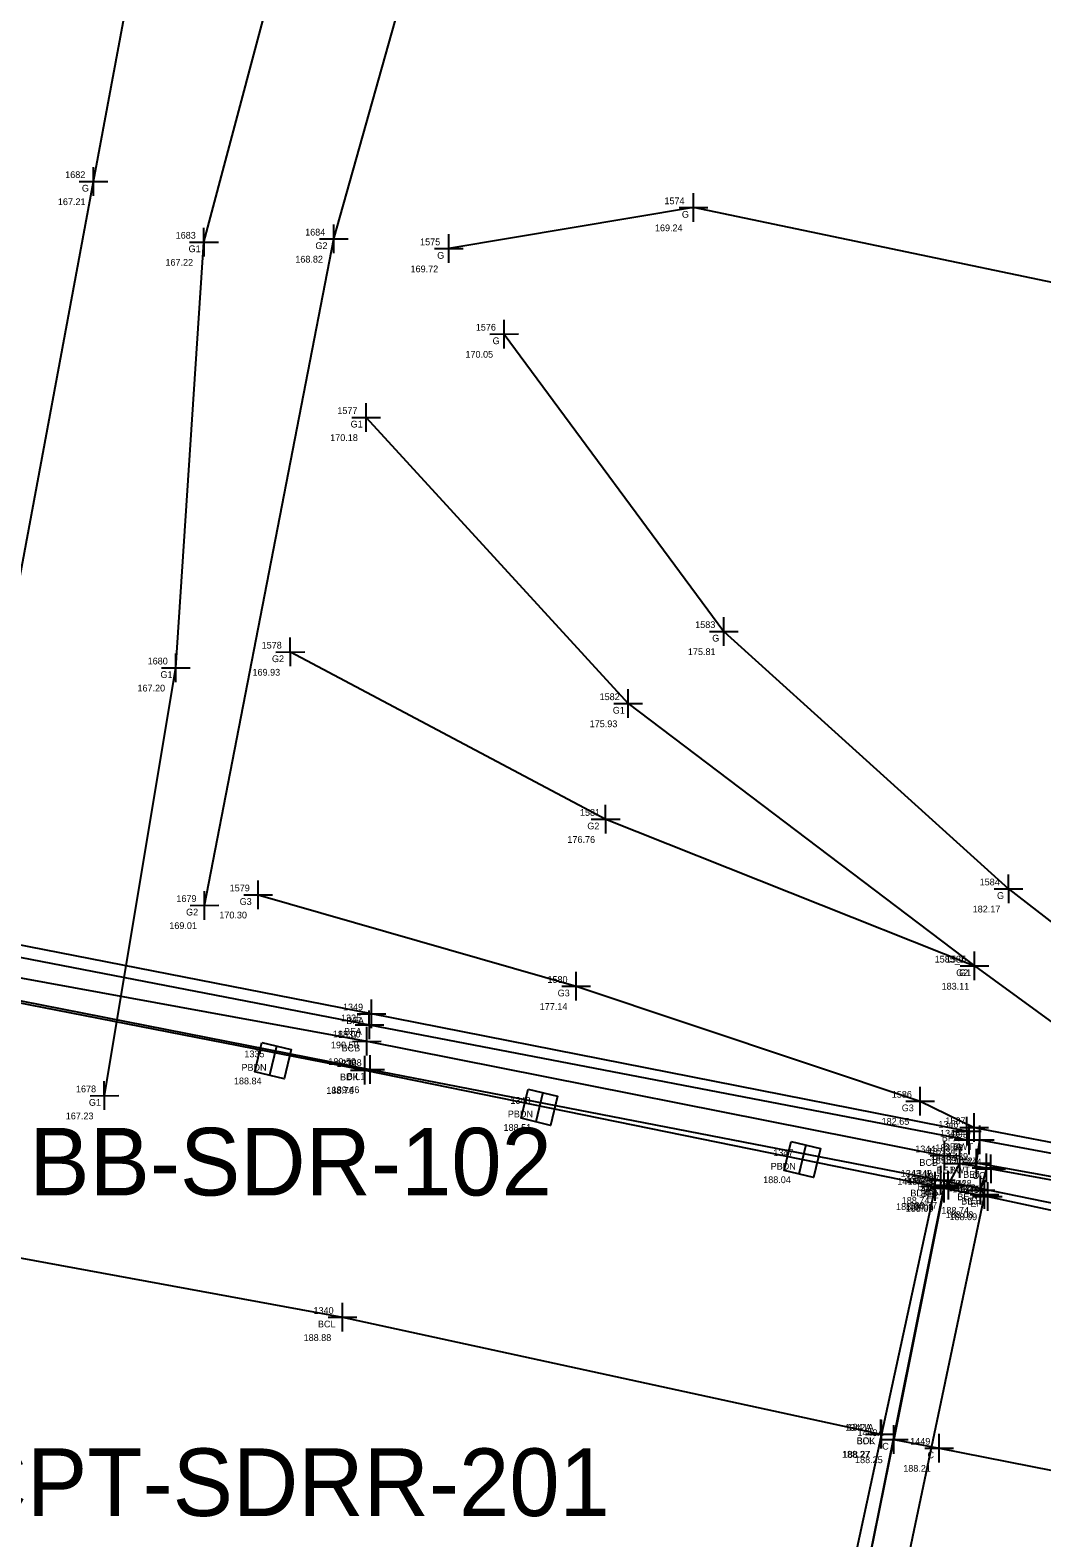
# Model space of a CAD drawing. Extents: x 1157913 to 1159198, y 600595 to 601244.
# Drawn here: x 1158682.7 to 1158727.6, y 600886 to 600952.9 of the extents above; entities that cross this region are included whole.
import ezdxf

# ---------------------------------------------------------------- set-up
doc = ezdxf.new("R2010")
doc.units = 0
for name, color, linetype in [('Default', 7, 'Continuous'), ('S_Bridge_Centerline', 7, 'Continuous'), ('S_Bridge_Curb', 7, 'Continuous'), ('S_Bridge_Deck', 7, 'Continuous'), ('S_Bridge_Downspout', 7, 'Continuous'), ('S_Bridge_ExpansionJoint', 7, 'Continuous'), ('S_Bridge_Fascia', 7, 'Continuous'), ('S_Bridge_Rail', 7, 'Continuous'), ('S_Bridge_Wingwall', 7, 'Continuous'), ('S_Curb_Type_2', 7, 'Continuous'), ('S_Field_Code', 7, 'Continuous'), ('S_Ground_Elevation', 7, 'Continuous'), ('S_Ground_LevelString', 7, 'Continuous'), ('S_Guardrail_Beam', 7, 'Continuous'), ('S_Point_Elevation', 7, 'Continuous'), ('S_Point_Name', 7, 'Continuous'), ('S_Roadway_Centerline', 7, 'Continuous'), ('S_Roadway_Edge_Pavement', 7, 'Continuous'), ('S_Survey_Shot', 7, 'Continuous'), ('S_Text', 7, 'Continuous')]:
    doc.layers.add(name, color=color, linetype=linetype)

msp = doc.modelspace()

# ---------------------------------------------------------------- linework, layer by layer
at = {"layer": 'Default'}
for p, q in [((1158693.515, 600907.201), (1158693.515, 600907.201)), ((1158705.332, 600905.136), (1158705.332, 600905.136)), ((1158716.992, 600902.818), (1158716.992, 600902.818))]:
    msp.add_line(p, q, dxfattribs=at)
at = {"layer": 'S_Bridge_Centerline'}
msp.add_lwpolyline([(1158481.195, 600937.121), (1158507.351, 600932.296), (1158531.006, 600927.652), (1158554.323, 600923.112), (1158577.507, 600918.68), (1158601.407, 600914.027), (1158625.013, 600909.477), (1158647.737, 600904.925), (1158672.228, 600900.301), (1158696.593, 600895.817), (1158720.484, 600890.638)], dxfattribs=at)
at = {"layer": 'S_Bridge_Curb'}
msp.add_lwpolyline([(1158483.161, 600950.18), (1158509.184, 600944.847), (1158532.763, 600940.379), (1158556.45, 600935.563), (1158579.829, 600931.057), (1158603.376, 600926.445), (1158626.911, 600921.776), (1158650.768, 600917.187), (1158674.064, 600912.392), (1158697.671, 600908.06), (1158723.302, 600902.985)], dxfattribs=at)
at = {"layer": 'S_Bridge_Deck'}
msp.add_lwpolyline([(1158483.154, 600948.642), (1158508.91, 600943.661), (1158532.625, 600939.025), (1158556.015, 600934.45), (1158579.602, 600929.788), (1158603.216, 600925.172), (1158626.871, 600920.52), (1158650.274, 600915.846), (1158673.938, 600911.396), (1158697.587, 600906.777), (1158722.887, 600901.626), (1158720.511, 600890.631), (1158717.86, 600878.361), (1158692.562, 600883.367), (1158669.405, 600887.913), (1158645.122, 600892.525), (1158622.108, 600897.299), (1158598.216, 600901.842), (1158574.819, 600906.519), (1158551.011, 600911.144), (1158527.523, 600915.567), (1158503.608, 600920.228), (1158478.738, 600925.244), (1158480.987, 600937.158)], close=True, dxfattribs=at)
at = {"layer": 'S_Bridge_Downspout'}
for p, q in [((1158693.67, 600907.849), (1158693.359, 600906.553)), ((1158705.487, 600905.784), (1158705.176, 600904.488)), ((1158717.147, 600903.466), (1158716.836, 600902.169))]:
    msp.add_line(p, q, dxfattribs=at)
for points in [[(1158693.022, 600908.005), (1158694.319, 600907.694), (1158694.007, 600906.397), (1158692.711, 600906.708)], [(1158704.839, 600905.94), (1158706.136, 600905.629), (1158705.824, 600904.332), (1158704.528, 600904.644)], [(1158716.499, 600903.622), (1158717.796, 600903.31), (1158717.484, 600902.014), (1158716.188, 600902.325)]]:
    msp.add_lwpolyline(points, close=True, dxfattribs=at)
at = {"layer": 'S_Bridge_ExpansionJoint'}
msp.add_lwpolyline([(1158725.16, 600902.453), (1158724.901, 600901.46), (1158725.074, 600901.268), (1158720.121, 600877.707), (1158720.119, 600877.751), (1158719.866, 600876.577), (1158718.73, 600876.808), (1158718.834, 600877.869), (1158718.598, 600878.263), (1158723.284, 600901.606), (1158723.471, 600901.679), (1158723.981, 600902.642)], close=True, dxfattribs=at)
at = {"layer": 'S_Bridge_Fascia'}
msp.add_lwpolyline([(1158482.861, 600951.354), (1158482.898, 600951.287), (1158509.367, 600945.979), (1158532.925, 600941.176), (1158556.366, 600936.562), (1158579.862, 600931.952), (1158603.5, 600927.221), (1158627.041, 600922.676), (1158650.576, 600918.007), (1158674.159, 600913.359), (1158697.787, 600908.797), (1158724.39, 600903.681), (1158724.298, 600904.075), (1158697.887, 600909.28), (1158674.374, 600913.874), (1158650.514, 600918.558), (1158627.158, 600923.073), (1158603.563, 600927.819), (1158579.96, 600932.392), (1158556.434, 600937.017), (1158532.882, 600941.581), (1158509.466, 600946.154)], close=True, dxfattribs=at)
at = {"layer": 'S_Bridge_Rail'}
msp.add_lwpolyline([(1158482.805, 600948.902), (1158509.002, 600943.778), (1158532.726, 600939.143), (1158579.85, 600929.84), (1158603.334, 600925.337), (1158626.819, 600920.746), (1158650.464, 600916.056), (1158674.206, 600911.454), (1158697.827, 600906.811), (1158723.142, 600901.902)], dxfattribs=at)
at = {"layer": 'S_Bridge_Wingwall'}
msp.add_lwpolyline([(1158724.724, 600902.653), (1158724.864, 600903.69), (1158734.549, 600901.881), (1158734.38, 600900.915)], close=True, dxfattribs=at)
at = {"layer": 'S_Curb_Type_2'}
msp.add_lwpolyline([(1158725.365, 600902.406), (1158734.123, 600900.806)], dxfattribs=at)
at = {"layer": 'S_Ground_Elevation'}
for points in [[(1158677.11, 600904.725), (1158681.901, 600926.567), (1158685.55, 600946.209), (1158690.749, 600974.108), (1158693.147, 600986.071), (1158701.123, 601024.221), (1158705.062, 601044.921), (1158714.653, 601091.459), (1158722.945, 601141.975), (1158734.939, 601204.822)], [(1158686.031, 600905.649), (1158689.206, 600924.63), (1158690.452, 600943.52), (1158697.926, 600971.62), (1158698.862, 600985.91), (1158705.062, 601022.477), (1158708.833, 601044.151), (1158718.556, 601089.986), (1158726.939, 601141.559), (1158739.749, 601204.844)], [(1158690.473, 600914.092), (1158696.21, 600943.659), (1158700.07, 600957.392), (1158701.342, 600965.961), (1158702.799, 600967.609), (1158714.854, 600964.534), (1158729.595, 600958.711)], [(1159148.387, 600827.64), (1159092.305, 600843.388), (1159023.639, 600857.423), (1158956.467, 600873.915), (1158901.674, 600888.215), (1158826.796, 600914.424), (1158787.654, 600925.882), (1158774.944, 600931.981), (1158737.918, 600939.668), (1158712.165, 600945.049), (1158701.311, 600943.228)], [(1158703.769, 600939.439), (1158713.512, 600926.246), (1158726.146, 600914.827), (1158737.183, 600906.281)], [(1158697.641, 600935.742), (1158709.272, 600923.047), (1158724.634, 600911.404), (1158732.975, 600905.326)], [(1158694.282, 600925.333), (1158708.271, 600917.914), (1158724.634, 600911.404)], [(1158692.85, 600914.562), (1158706.956, 600910.503), (1158722.22, 600905.407), (1158724.615, 600904.235), (1158733.258, 600902.581), (1158734.697, 600902.369), (1158734.457, 600900.754)]]:
    msp.add_lwpolyline(points, dxfattribs=at)
at = {"layer": 'S_Ground_LevelString'}
msp.add_line((1158723.29, 600901.545), (1158723.29, 600901.545), dxfattribs=at)
for points in [[(1158723.29, 600901.545), (1158721.055, 600890.395)], [(1158718.555, 600878.077), (1158721.055, 600890.395)]]:
    msp.add_lwpolyline(points, dxfattribs=at)
at = {"layer": 'S_Guardrail_Beam'}
msp.add_lwpolyline([(1158723.142, 600901.902), (1158735.673, 600899.33), (1158779.708, 600892.778), (1158821.057, 600885.008), (1158872.579, 600874.816), (1158921.179, 600864.906), (1158974.289, 600854.576), (1159026.528, 600844.124), (1159039.988, 600841.695), (1159053.262, 600839.632), (1159065.358, 600838.096), (1159078.578, 600837.332)], dxfattribs=at)
at = {"layer": 'S_Roadway_Centerline'}
msp.add_lwpolyline([(1158721.055, 600890.395), (1158723.064, 600890.013), (1158776.46, 600879.509), (1158819.528, 600871.149), (1158868.15, 600861.085), (1158918.713, 600851.111), (1158970.46, 600840.7), (1159022.781, 600830.456), (1159075.358, 600819.935), (1159137.497, 600807.122), (1159188.145, 600796.962)], dxfattribs=at)
at = {"layer": 'S_Roadway_Edge_Pavement'}
msp.add_lwpolyline([(1158723.29, 600901.545), (1158725.228, 600901.176), (1158730.919, 600899.955), (1158734.277, 600898.718), (1158779.347, 600889.226), (1158821.037, 600881.144), (1158871.084, 600871.138), (1158921.105, 600861.196), (1158972.945, 600850.848), (1159025.625, 600840.648), (1159077.094, 600830.514), (1159119.992, 600821.415), (1159145.866, 600816.084), (1159193.179, 600806.656)], dxfattribs=at)
at = {"layer": 'S_Survey_Shot'}
for p, q in [((1158685.552, 600945.573), (1158685.549, 600946.846)), ((1158684.914, 600946.208), (1158686.187, 600946.211)), ((1158685.55, 600946.209), (1158685.55, 600946.209)), ((1158712.166, 600944.413), (1158712.164, 600945.685)), ((1158711.529, 600945.048), (1158712.801, 600945.05)), ((1158712.165, 600945.049), (1158712.165, 600945.049)), ((1158690.453, 600942.883), (1158690.45, 600944.156)), ((1158696.211, 600943.023), (1158696.208, 600944.296)), ((1158689.816, 600943.518), (1158691.088, 600943.521)), ((1158690.452, 600943.52), (1158690.452, 600943.52)), ((1158695.574, 600943.658), (1158696.846, 600943.661)), ((1158696.21, 600943.659), (1158696.21, 600943.659)), ((1158701.312, 600942.592), (1158701.309, 600943.865)), ((1158700.674, 600943.227), (1158701.947, 600943.23)), ((1158701.311, 600943.228), (1158701.311, 600943.228)), ((1158703.77, 600938.803), (1158703.768, 600940.076)), ((1158703.133, 600939.438), (1158704.405, 600939.441)), ((1158703.769, 600939.439), (1158703.769, 600939.439)), ((1158697.643, 600935.105), (1158697.64, 600936.378)), ((1158697.005, 600935.74), (1158698.278, 600935.743)), ((1158697.641, 600935.742), (1158697.641, 600935.742)), ((1158713.514, 600925.61), (1158713.511, 600926.883)), ((1158712.876, 600926.245), (1158714.149, 600926.248)), ((1158713.512, 600926.246), (1158713.512, 600926.246)), ((1158694.283, 600924.697), (1158694.281, 600925.969)), ((1158689.207, 600923.993), (1158689.205, 600925.266)), ((1158693.646, 600925.332), (1158694.918, 600925.334)), ((1158694.282, 600925.333), (1158694.282, 600925.333)), ((1158688.57, 600924.628), (1158689.842, 600924.631)), ((1158689.206, 600924.63), (1158689.206, 600924.63)), ((1158709.274, 600922.411), (1158709.271, 600923.683)), ((1158708.636, 600923.046), (1158709.908, 600923.049)), ((1158709.272, 600923.047), (1158709.272, 600923.047)), ((1158708.272, 600917.278), (1158708.269, 600918.55)), ((1158707.634, 600917.913), (1158708.907, 600917.915)), ((1158708.271, 600917.914), (1158708.271, 600917.914)), ((1158726.148, 600914.191), (1158726.145, 600915.464)), ((1158690.474, 600913.456), (1158690.472, 600914.728)), ((1158692.852, 600913.925), (1158692.849, 600915.198)), ((1158725.51, 600914.826), (1158726.783, 600914.829)), ((1158726.146, 600914.827), (1158726.146, 600914.827)), ((1158689.837, 600914.091), (1158691.109, 600914.094)), ((1158690.473, 600914.092), (1158690.473, 600914.092)), ((1158692.214, 600914.56), (1158693.487, 600914.563)), ((1158692.85, 600914.562), (1158692.85, 600914.562)), ((1158724.636, 600910.767), (1158724.633, 600912.04)), ((1158724.636, 600910.767), (1158724.633, 600912.04)), ((1158723.998, 600911.402), (1158725.27, 600911.405)), ((1158723.998, 600911.402), (1158725.27, 600911.405)), ((1158724.634, 600911.404), (1158724.634, 600911.404)), ((1158724.634, 600911.404), (1158724.634, 600911.404)), ((1158706.958, 600909.867), (1158706.955, 600911.139)), ((1158706.32, 600910.502), (1158707.593, 600910.504)), ((1158706.956, 600910.503), (1158706.956, 600910.503)), ((1158697.788, 600908.161), (1158697.785, 600909.433)), ((1158697.889, 600908.644), (1158697.886, 600909.916)), ((1158697.151, 600908.796), (1158698.423, 600908.798)), ((1158697.251, 600909.279), (1158698.524, 600909.282)), ((1158697.672, 600907.424), (1158697.67, 600908.696)), ((1158697.787, 600908.797), (1158697.787, 600908.797)), ((1158697.887, 600909.28), (1158697.887, 600909.28)), ((1158697.035, 600908.059), (1158698.307, 600908.062)), ((1158697.671, 600908.06), (1158697.671, 600908.06)), ((1158697.588, 600906.141), (1158697.586, 600907.414)), ((1158697.828, 600906.175), (1158697.825, 600907.447)), ((1158696.951, 600906.776), (1158698.223, 600906.779)), ((1158697.191, 600906.81), (1158698.463, 600906.813)), ((1158697.587, 600906.777), (1158697.587, 600906.777)), ((1158697.827, 600906.811), (1158697.827, 600906.811)), ((1158686.032, 600905.013), (1158686.03, 600906.285)), ((1158722.221, 600904.771), (1158722.219, 600906.043)), ((1158685.395, 600905.648), (1158686.667, 600905.65)), ((1158686.031, 600905.649), (1158686.031, 600905.649)), ((1158721.584, 600905.406), (1158722.856, 600905.408)), ((1158722.22, 600905.407), (1158722.22, 600905.407)), ((1158724.3, 600903.439), (1158724.297, 600904.711)), ((1158724.616, 600903.599), (1158724.613, 600904.871)), ((1158723.662, 600904.074), (1158724.935, 600904.076)), ((1158723.979, 600904.234), (1158725.251, 600904.236)), ((1158724.298, 600904.075), (1158724.298, 600904.075)), ((1158724.391, 600903.045), (1158724.389, 600904.317)), ((1158724.615, 600904.235), (1158724.615, 600904.235)), ((1158724.866, 600903.054), (1158724.863, 600904.326)), ((1158723.304, 600902.349), (1158723.301, 600903.622)), ((1158723.754, 600903.679), (1158725.026, 600903.682)), ((1158724.228, 600903.689), (1158725.501, 600903.691)), ((1158724.39, 600903.681), (1158724.39, 600903.681)), ((1158724.725, 600902.017), (1158724.722, 600903.29)), ((1158724.864, 600903.69), (1158724.864, 600903.69)), ((1158722.666, 600902.984), (1158723.939, 600902.987)), ((1158723.302, 600902.985), (1158723.302, 600902.985)), ((1158723.345, 600902.64), (1158724.617, 600902.643)), ((1158723.983, 600902.005), (1158723.98, 600903.278)), ((1158723.981, 600902.642), (1158723.981, 600902.642)), ((1158724.087, 600902.652), (1158725.36, 600902.655)), ((1158724.724, 600902.653), (1158724.724, 600902.653)), ((1158725.161, 600901.817), (1158725.159, 600903.089)), ((1158725.367, 600901.77), (1158725.364, 600903.042)), ((1158722.889, 600900.989), (1158722.886, 600902.262)), ((1158723.144, 600901.266), (1158723.141, 600902.539)), ((1158723.144, 600901.266), (1158723.141, 600902.539)), ((1158723.286, 600900.969), (1158723.283, 600902.242)), ((1158723.291, 600900.908), (1158723.289, 600902.181)), ((1158723.291, 600900.908), (1158723.289, 600902.181)), ((1158723.473, 600901.043), (1158723.47, 600902.316)), ((1158724.524, 600902.452), (1158725.796, 600902.454)), ((1158724.729, 600902.405), (1158726.001, 600902.408)), ((1158724.903, 600900.824), (1158724.9, 600902.097)), ((1158725.16, 600902.453), (1158725.16, 600902.453)), ((1158725.365, 600902.406), (1158725.365, 600902.406)), ((1158722.251, 600901.624), (1158723.524, 600901.627)), ((1158722.506, 600901.901), (1158723.779, 600901.904)), ((1158722.506, 600901.901), (1158723.779, 600901.904)), ((1158722.648, 600901.604), (1158723.92, 600901.607)), ((1158722.654, 600901.543), (1158723.926, 600901.546)), ((1158722.654, 600901.543), (1158723.926, 600901.546)), ((1158722.835, 600901.678), (1158724.108, 600901.681)), ((1158722.887, 600901.626), (1158722.887, 600901.626)), ((1158723.142, 600901.902), (1158723.142, 600901.902)), ((1158723.142, 600901.902), (1158723.142, 600901.902)), ((1158723.284, 600901.606), (1158723.284, 600901.606)), ((1158723.29, 600901.545), (1158723.29, 600901.545)), ((1158723.29, 600901.545), (1158723.29, 600901.545)), ((1158723.471, 600901.679), (1158723.471, 600901.679)), ((1158724.265, 600901.459), (1158725.537, 600901.462)), ((1158724.901, 600901.46), (1158724.901, 600901.46)), ((1158725.075, 600900.632), (1158725.073, 600901.905)), ((1158725.23, 600900.54), (1158725.227, 600901.812)), ((1158724.438, 600901.267), (1158725.71, 600901.27)), ((1158724.592, 600901.174), (1158725.865, 600901.177)), ((1158725.074, 600901.268), (1158725.074, 600901.268)), ((1158725.228, 600901.176), (1158725.228, 600901.176)), ((1158696.594, 600895.181), (1158696.591, 600896.453)), ((1158695.957, 600895.816), (1158697.229, 600895.819)), ((1158696.593, 600895.817), (1158696.593, 600895.817)), ((1158720.485, 600890.001), (1158720.483, 600891.274)), ((1158720.513, 600889.995), (1158720.51, 600891.267)), ((1158719.848, 600890.636), (1158721.12, 600890.639)), ((1158719.875, 600890.63), (1158721.148, 600890.632)), ((1158720.484, 600890.638), (1158720.484, 600890.638)), ((1158720.511, 600890.631), (1158720.511, 600890.631)), ((1158721.056, 600889.758), (1158721.053, 600891.031)), ((1158723.066, 600889.377), (1158723.063, 600890.649)), ((1158720.419, 600890.393), (1158721.691, 600890.396)), ((1158721.055, 600890.395), (1158721.055, 600890.395)), ((1158722.428, 600890.012), (1158723.7, 600890.014)), ((1158723.064, 600890.013), (1158723.064, 600890.013))]:
    msp.add_line(p, q, dxfattribs=at)

# ---------------------------------------------------------------- texts
at = {"layer": 'S_Field_Code'}
for s, p in [('G', (1158685.035, 600945.759)), ('G', (1158711.65, 600944.599)), ('G2', (1158695.395, 600943.209)), ('G1', (1158689.767, 600943.07)), ('G', (1158700.796, 600942.778)), ('G', (1158703.254, 600938.989)), ('G1', (1158696.956, 600935.292)), ('G', (1158712.998, 600925.796)), ('G2', (1158693.467, 600924.883)), ('G1', (1158688.521, 600924.18)), ('G1', (1158708.587, 600922.597)), ('G2', (1158707.456, 600917.464)), ('G', (1158725.631, 600914.377)), ('G3', (1158692.035, 600914.112)), ('G2', (1158689.658, 600913.642)), ('G2', (1158723.819, 600910.954)), ('G1', (1158723.949, 600910.954)), ('G3', (1158706.141, 600910.053)), ('BFA', (1158696.67, 600908.347)), ('BFA', (1158696.77, 600908.83)), ('BCB', (1158696.556, 600907.61)), ('PBDN', (1158692.114, 600906.751)), ('BDK', (1158696.486, 600906.327)), ('BIL1', (1158696.785, 600906.361)), ('G1', (1158685.346, 600905.199)), ('PBDN', (1158703.931, 600904.686)), ('G3', (1158721.405, 600904.957)), ('G3', (1158723.8, 600903.785)), ('BFA', (1158723.181, 600903.625)), ('BFA', (1158723.273, 600903.231)), ('BWT', (1158723.679, 600903.24)), ('PBDN', (1158715.591, 600902.368)), ('BCB', (1158722.187, 600902.535)), ('BEJ', (1158722.951, 600902.192)), ('BWT', (1158723.538, 600902.203)), ('BEJ', (1158724.13, 600902.003)), ('CC', (1158724.536, 600901.956)), ('BDK', (1158721.787, 600901.176)), ('BIL1', (1158722.101, 600901.452)), ('BEJ', (1158722.254, 600901.156)), ('GB', (1158722.328, 600901.452)), ('BEJ', (1158722.442, 600901.229)), ('EP', (1158722.503, 600901.095)), ('L', (1158722.818, 600901.095)), ('BEJ', (1158723.871, 600901.01)), ('BEJ', (1158724.044, 600900.818)), ('EP', (1158724.442, 600900.726)), ('BCL', (1158695.506, 600895.367)), ('BCL', (1158719.398, 600890.188)), ('BDK', (1158719.411, 600890.181)), ('C', (1158720.54, 600889.945)), ('C', (1158722.549, 600889.563))]:
    msp.add_text(s, height=0.3, dxfattribs=at).set_placement(p)
at = {"layer": 'S_Point_Elevation'}
for s, p in [('167.21', (1158683.97, 600945.159)), ('169.24', (1158710.457, 600943.999)), ('167.22', (1158688.742, 600942.47)), ('168.82', (1158694.502, 600942.609)), ('169.72', (1158699.615, 600942.178)), ('170.05', (1158702.05, 600938.389)), ('170.18', (1158696.05, 600934.692)), ('175.81', (1158711.918, 600925.196)), ('169.93', (1158692.603, 600924.283)), ('167.20', (1158687.499, 600923.58)), ('175.93', (1158707.562, 600921.997)), ('176.76', (1158706.573, 600916.864)), ('182.17', (1158724.552, 600913.777)), ('169.01', (1158688.912, 600913.042)), ('170.30', (1158691.131, 600913.512)), ('183.11', (1158723.172, 600910.354)), ('183.11', (1158723.172, 600910.354)), ('177.14', (1158705.346, 600909.453)), ('190.50', (1158696.084, 600907.747)), ('188.00', (1158696.17, 600908.23)), ('189.50', (1158695.966, 600907.01)), ('188.84', (1158691.779, 600906.151)), ('188.76', (1158695.877, 600905.727)), ('189.46', (1158696.119, 600905.761)), ('167.23', (1158684.321, 600904.599)), ('182.65', (1158720.512, 600904.357)), ('188.51', (1158703.74, 600904.086)), ('187.34', (1158722.56, 600903.025)), ('183.28', (1158722.893, 600903.185)), ('189.79', (1158722.694, 600902.631)), ('189.85', (1158723.157, 600902.64)), ('188.04', (1158715.258, 600901.768)), ('188.79', (1158721.592, 600901.935)), ('188.77', (1158722.255, 600901.592)), ('189.84', (1158723.002, 600901.603)), ('188.76', (1158723.45, 600901.403)), ('188.75', (1158723.641, 600901.356)), ('188.04', (1158721.154, 600900.576)), ('188.74', (1158721.404, 600900.852)), ('188.74', (1158721.404, 600900.852)), ('188.09', (1158721.579, 600900.556)), ('188.09', (1158721.585, 600900.495)), ('188.09', (1158721.585, 600900.495)), ('188.77', (1158721.745, 600900.629)), ('188.74', (1158723.163, 600900.41)), ('188.08', (1158723.354, 600900.218)), ('188.09', (1158723.523, 600900.126)), ('188.88', (1158694.871, 600894.767)), ('188.27', (1158718.76, 600889.588)), ('188.27', (1158718.787, 600889.581)), ('188.25', (1158719.333, 600889.345)), ('188.21', (1158721.472, 600888.963))]:
    msp.add_text(s, height=0.3, dxfattribs=at).set_placement(p)
at = {"layer": 'S_Point_Name'}
for s, p in [('1682', (1158684.294, 600946.359)), ('1574', (1158710.878, 600945.199)), ('1684', (1158694.939, 600943.809)), ('1683', (1158689.195, 600943.67)), ('1575', (1158700.038, 600943.378)), ('1576', (1158702.51, 600939.59)), ('1577', (1158696.366, 600935.892)), ('1583', (1158712.242, 600926.396)), ('1578', (1158693.009, 600925.483)), ('1680', (1158687.952, 600924.78)), ('1582', (1158708.001, 600923.197)), ('1581', (1158707.13, 600918.064)), ('1579', (1158691.591, 600914.712)), ('1584', (1158724.861, 600914.977)), ('1679', (1158689.228, 600914.242)), ('1585_1', (1158722.865, 600911.554)), ('1585', (1158723.363, 600911.554)), ('1580', (1158705.688, 600910.653)), ('1349', (1158696.617, 600909.43)), ('1336', (1158696.53, 600908.947)), ('1337', (1158696.398, 600908.21)), ('1335', (1158692.244, 600907.351)), ('1339', (1158696.33, 600906.927)), ('1338', (1158696.556, 600906.961)), ('1678', (1158684.772, 600905.799)), ('1348', (1158704.047, 600905.286)), ('1586', (1158720.963, 600905.557)), ('1587', (1158723.342, 600904.385)), ('1346', (1158723.028, 600904.225)), ('1345', (1158723.105, 600903.831)), ('1440', (1158723.568, 600903.84)), ('1344', (1158722.003, 600903.135)), ('1347', (1158715.704, 600902.968)), ('1438', (1158722.696, 600902.792)), ('1439', (1158723.453, 600902.803)), ('1427', (1158723.873, 600902.603)), ('1444', (1158724.052, 600902.556)), ('1445A_1', (1158721.207, 600901.695)), ('1343_1', (1158721.359, 600902.052)), ('1342', (1158721.602, 600901.776)), ('1445A', (1158721.66, 600901.695)), ('1343', (1158721.858, 600902.052)), ('1436', (1158722.013, 600901.756)), ('1437', (1158722.184, 600901.829)), ('1428', (1158723.616, 600901.61)), ('1429', (1158723.803, 600901.418)), ('1445', (1158723.929, 600901.326)), ('1340', (1158695.31, 600895.967)), ('1342A', (1158718.896, 600890.781)), ('1341A', (1158718.998, 600890.788)), ('1449A', (1158719.439, 600890.545)), ('1449', (1158721.779, 600890.163))]:
    msp.add_text(s, height=0.3, dxfattribs=at).set_placement(p)
at = {"layer": 'S_Text'}
for s, p in [('BB-SDR-102', (1158682.698, 600901.22)), ('CPT-SDRR-201', (1158679.702, 600886.999))]:
    msp.add_text(s, height=3, dxfattribs=at).set_placement(p)

doc.saveas('drawing.dxf')
